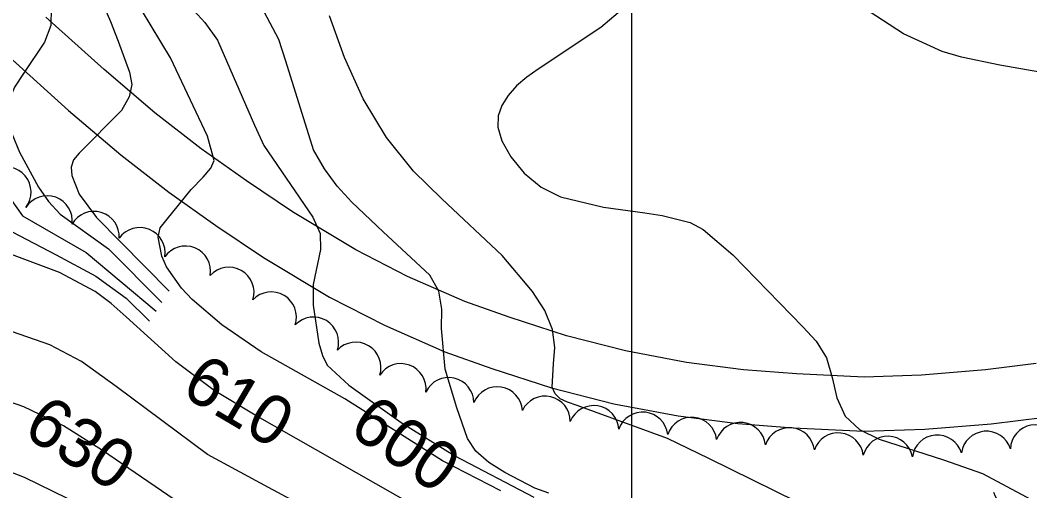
# Model space of a CAD drawing. Extents: x 79600 to 91800, y 75600 to 84400.
# Drawn here: x 87751.3 to 88162.1, y 79108.8 to 79300.2 of the extents above; entities that cross this region are included whole.
import ezdxf

# ---------------------------------------------------------------- set-up
doc = ezdxf.new("R2010")
doc.units = 0
for name, color, linetype in [('080-090$0$GRID', 7, 'Continuous'), ('080-090$0$INDEX', 7, 'Continuous'), ('080-090$0$INDXLBL', 7, 'Continuous'), ('080-090$0$INTER', 7, 'Continuous'), ('080-090$0$ROAD', 7, 'Continuous'), ('080-090$0$TREES', 7, 'Continuous')]:
    doc.layers.add(name, color=color, linetype=linetype)

msp = doc.modelspace()

# ---------------------------------------------------------------- linework, layer by layer
at = {"layer": '080-090$0$GRID'}
msp.add_line((88000, 80000), (88000, 76000), dxfattribs=at)
at = {"layer": '080-090$0$INDEX'}
for points in [[(87946.82, 79108.78), (87923.08, 79121.05), (87883.37, 79146.18), (87849.37, 79165.27), (87833.39, 79176.35), (87821.22, 79186.66), (87816.87, 79191.16), (87810.84, 79199.94), (87808.96, 79204.27), (87807.39, 79211.96), (87808.21, 79215.71), (87820.82, 79231.4), (87825.72, 79236.4), (87828.89, 79240), (87830.18, 79243.13), (87827.55, 79252.98), (87812.43, 79284.93), (87792.75, 79317.56)], [(87912.66, 79102.13), (87846.87, 79139.6), (87830.27, 79149.6), (87814.61, 79161.27), (87794.43, 79179.51), (87788.26, 79184.96), (87781.84, 79189.81), (87767.29, 79197.56), (87742.12, 79206.9)], [(87902.65, 79083.15), (87852.26, 79110.09), (87827.54, 79123.61), (87790.4, 79151.18), (87776.22, 79161.39), (87763.32, 79168.18), (87748.14, 79173.47)], [(87824.61, 79097.97), (87784.76, 79125.19), (87768.89, 79135.25), (87752.83, 79142.96), (87737.46, 79148.3)], [(87770.52, 79105.71), (87752.98, 79114.25), (87743.95, 79117.71)]]:
    msp.add_lwpolyline(points, dxfattribs=at)
at = {"layer": '080-090$0$INTER'}
for points in [[(87679.29, 79325.65), (87711.71, 79268.31), (87724.75, 79243), (87728.59, 79235.2), (87732.31, 79228.35), (87736.51, 79222.41), (87741.94, 79217.3), (87765.98, 79204.84), (87782.04, 79196.17), (87794.42, 79187.1), (87803.91, 79177.78)], [(88014.89, 79320.55), (87987.52, 79297.2), (87962.06, 79280.26), (87957.38, 79277.05), (87953.28, 79273.51), (87949.87, 79269.64), (87947.31, 79265.57), (87945.8, 79261.33), (87945.68, 79256.64), (87947.3, 79251.11), (87950.93, 79244.62), (87956.35, 79238), (87963.2, 79232.3), (87971.14, 79228.32), (87988.6, 79224.12), (88005.39, 79221.8), (88012.55, 79220.82), (88023.87, 79217.98), (88029.22, 79215.03), (88041.22, 79204.82), (88069.73, 79175.51), (88075.18, 79169.63), (88079.31, 79162.83), (88081.68, 79154.84), (88083.61, 79146.56), (88086.89, 79139.23), (88092.8, 79133.75), (88100.73, 79129.81), (88127.02, 79121.45), (88142.81, 79115.89), (88180.37, 79095.72)], [(87966.44, 79107.83), (87960.7, 79109.93), (87948.42, 79116.19), (87942.02, 79120.27), (87936.73, 79124.89), (87933.25, 79130.05), (87928.93, 79142.53), (87924.16, 79158.28), (87922.72, 79174.87), (87922.87, 79182.69), (87921.66, 79189.94), (87917.95, 79196.51), (87899, 79214.19), (87886.18, 79226.24), (87880.32, 79232.75), (87875.07, 79239.79), (87870.65, 79247.54), (87859.39, 79283.56), (87856.49, 79292.42), (87843.38, 79317.28)], [(88166.22, 79279.05), (88149.89, 79281.96), (88134.27, 79285.17), (88126.48, 79287.51), (88110.71, 79294.73), (88079.24, 79315.25)], [(87784.4, 79308.14), (87787.98, 79299.64), (87791.11, 79291.67), (87793.76, 79284.7), (87795.79, 79279.03), (87796.65, 79274.08), (87795.69, 79269.06), (87792.54, 79263.47), (87775.22, 79246.18), (87772.95, 79243.48), (87772.01, 79240.47), (87772.24, 79237.1), (87775.26, 79229.45), (87782.29, 79220.02), (87811.92, 79190)], [(87820.48, 79305.81), (87826.41, 79299.34), (87831.62, 79292.03), (87846.59, 79257.54), (87850.43, 79249.29), (87870.39, 79220.16), (87873.35, 79213.5), (87873.49, 79206.95), (87870.55, 79192.66), (87870.46, 79184.29), (87872.86, 79168.87), (87874.27, 79163.78), (87876.25, 79159.96), (87884.97, 79151.76), (87906.36, 79136.53), (87928.15, 79123.07), (87960.27, 79106.23)], [(87707.63, 79302.67), (87706.39, 79297.44), (87708.37, 79290.94), (87737.33, 79244.79), (87745.3, 79230.4), (87752.18, 79220.7), (87778.07, 79205.68), (87806.62, 79181.92)], [(87763.91, 79305.04), (87763.76, 79298.09), (87761.21, 79291.26), (87752.69, 79278.56), (87748.99, 79272.97), (87746.63, 79267.41), (87746.15, 79261.28), (87747.83, 79254.16), (87751.03, 79246.53), (87758.67, 79232.36), (87762.76, 79226.45), (87767.61, 79221.3), (87787.25, 79207.24), (87808.91, 79185.41)], [(88182.96, 79047.33), (88031.53, 79121.93), (88014.69, 79130.14), (87977.94, 79143.53), (87973.91, 79144.85), (87970.97, 79146.28), (87968.93, 79148.21), (87967.8, 79151), (87968.32, 79160.45), (87968.82, 79167.06), (87967.93, 79174.4), (87964.77, 79182.08), (87959.79, 79189.82), (87947.43, 79204.51), (87922.83, 79227.62), (87911.29, 79238.84), (87900.31, 79252.47), (87890.9, 79268.19), (87883.27, 79285.1), (87877.19, 79302.02)]]:
    msp.add_lwpolyline(points, dxfattribs=at)
at = {"layer": '080-090$0$ROAD'}
for p, q in [((87785.44, 79280.1), (87761.78, 79301.48)), ((87746.72, 79285.44), (87770.94, 79263.55)), ((87806.05, 79262.58), (87785.44, 79280.1)), ((87770.94, 79263.55), (87792.17, 79245.5)), ((87824.9, 79247.95), (87806.05, 79262.58)), ((87792.17, 79245.5), (87811.79, 79230.27)), ((87843.38, 79234.85), (87824.9, 79247.95)), ((87862.1, 79222.31), (87843.38, 79234.85)), ((87811.79, 79230.27), (87830.89, 79216.73)), ((87887.83, 79206.77), (87862.1, 79222.31)), ((87830.89, 79216.73), (87850.28, 79203.74)), ((87850.28, 79203.74), (87877.14, 79187.52)), ((87908.94, 79196.02), (87887.83, 79206.77)), ((87932.2, 79185.75), (87908.94, 79196.02)), ((87877.14, 79187.52), (87899.5, 79176.14)), ((87950.27, 79179.41), (87932.2, 79185.75)), ((87973.58, 79171.78), (87950.27, 79179.41)), ((87899.5, 79176.14), (87924.1, 79165.27)), ((87997.58, 79165.71), (87973.58, 79171.78)), ((87924.1, 79165.27), (87943.21, 79158.57)), ((88022.44, 79161.05), (87997.58, 79165.71)), ((87943.21, 79158.57), (87967.46, 79150.64)), ((88045.62, 79158.01), (88022.44, 79161.05)), ((88067.13, 79156.33), (88045.62, 79158.01)), ((88144.08, 79157.98), (88118.08, 79155.86)), ((88164.74, 79160.54), (88144.08, 79157.98)), ((88094.62, 79155.06), (88067.13, 79156.33)), ((88118.08, 79155.86), (88094.62, 79155.06)), ((87967.46, 79150.64), (87992.86, 79144.22)), ((87992.86, 79144.22), (88018.98, 79139.31)), ((88018.98, 79139.31), (88043.34, 79136.12)), ((88146.33, 79136.09), (88168.3, 79138.81)), ((88043.34, 79136.12), (88065.77, 79134.37)), ((88065.77, 79134.37), (88094.49, 79133.04)), ((88094.49, 79133.04), (88119.35, 79133.89)), ((88119.35, 79133.89), (88146.33, 79136.09))]:
    msp.add_line(p, q, dxfattribs=at)
at = {"layer": '080-090$0$TREES'}
for centre, start, end in [((87745.47, 79230.31), 322.5639, 117.2032), ((87762.24, 79218.54), 352.6821, 147.3214), ((87781.34, 79212.21), 356.0042, 150.6435), ((87799.98, 79205.64), 350.5065, 145.1457), ((87818.5, 79198.09), 350.5065, 145.1457), ((87836.19, 79189.5), 343.0434, 137.6826), ((87853.43, 79179.46), 341.8773, 136.5166), ((87870.61, 79169.21), 341.8773, 136.5166), ((87887.81, 79159), 342.0601, 136.6993), ((87906.18, 79150.29), 352.5978, 147.2371), ((87925.63, 79144.63), 0.2855, 154.9247), ((87945.39, 79140.87), 3.5417, 158.1809), ((87964.86, 79137.07), 359.7262, 154.3654), ((87984.64, 79133.22), 3.6279, 158.2671), ((88004.57, 79130.58), 6.615, 161.2542), ((88024.46, 79128.46), 6.615, 161.2542), ((88044.35, 79126.35), 6.615, 161.2542), ((88064.24, 79124.24), 6.615, 161.2542), ((88164.41, 79125.44), 23.2398, 177.879), ((88084.12, 79122.12), 6.615, 161.2542), ((88104.23, 79120.74), 10.8653, 165.5045), ((88124.44, 79121.22), 17.1924, 171.8316), ((88144.38, 79122.79), 17.1924, 171.8316), ((88157.14, 79111.21), 196.4527, 351.092)]:
    msp.add_arc(centre, 10.25, start, end, dxfattribs=at)

# ---------------------------------------------------------------- texts
at = {"layer": '080-090$0$INDXLBL'}
for s, rotation, p in [('610', 329.4729, (87816.06, 79148.19)), ('630', 327.7966, (87751.72, 79131.79)), ('600', 325.0187, (87884.25, 79132.66))]:
    msp.add_text(s, height=20, rotation=rotation, dxfattribs=at).set_placement(p)

doc.saveas('drawing.dxf')
